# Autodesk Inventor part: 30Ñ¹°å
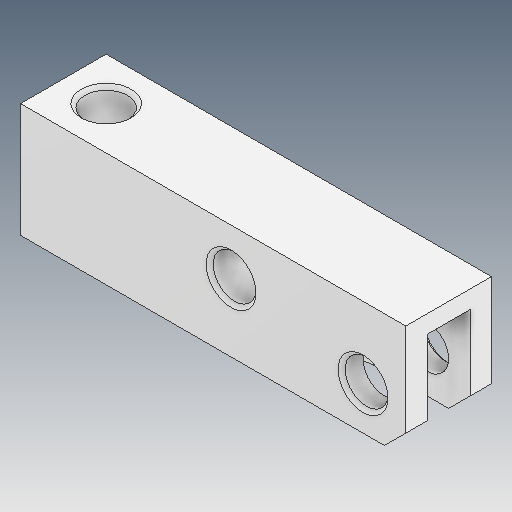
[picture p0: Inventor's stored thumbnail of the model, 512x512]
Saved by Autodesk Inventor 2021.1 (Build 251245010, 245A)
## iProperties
Created: 2021-05
Part Number: 30Ñ¹°å
Material: Ogólny
Document SubType Name: Modeling
Designer: user
Density: 1 g/cm^3
Appearance: Domyślna
Author: user
Revision Number: ÈÎºÎ
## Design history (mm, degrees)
feature "ÊäÈë1"
node "Bryła1"
